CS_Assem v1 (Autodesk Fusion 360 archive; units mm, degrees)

design "CS_Assem" references "Assem_Finial.ipt"
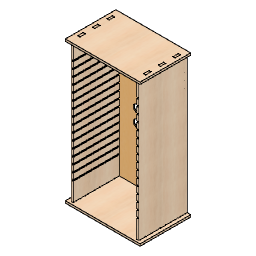
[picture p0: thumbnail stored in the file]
step "WorkingModel" bodies "Solid1", "Solid2", "Solid3", "Solid4", "Solid5"
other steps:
derived_base_feature "Derived Base Feature" bodies "Solid1", "Solid2", "Solid3", "Solid4", "Solid5"
named bodies: "Solid1", "Solid2", "Solid3", "Solid4", "Solid5"

design "Assem_Finial.ipt"
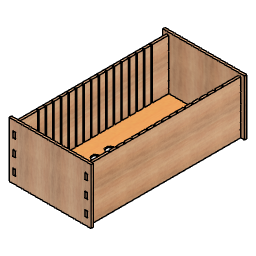
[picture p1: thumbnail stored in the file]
description: Part Number
part number: g2ocqgbw
named bodies: "Solid1", "Solid2", "Solid3", "Solid4", "Solid5"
